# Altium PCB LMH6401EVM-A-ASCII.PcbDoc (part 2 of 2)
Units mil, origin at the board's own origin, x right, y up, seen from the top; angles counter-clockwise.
Board outline 1307 x 2660 mil, 6 copper layers (Top Layer L1, Layer 2 GND L2, Layer 3 V+ L3, Layer 4 V- L4, Layer 5 GND L5, Bottom Layer L6), stack 56.6 mil thick; 69 components, 33 nets, 203 pads, 373 vias.
Unrouted connection lines stored in the file: 2.
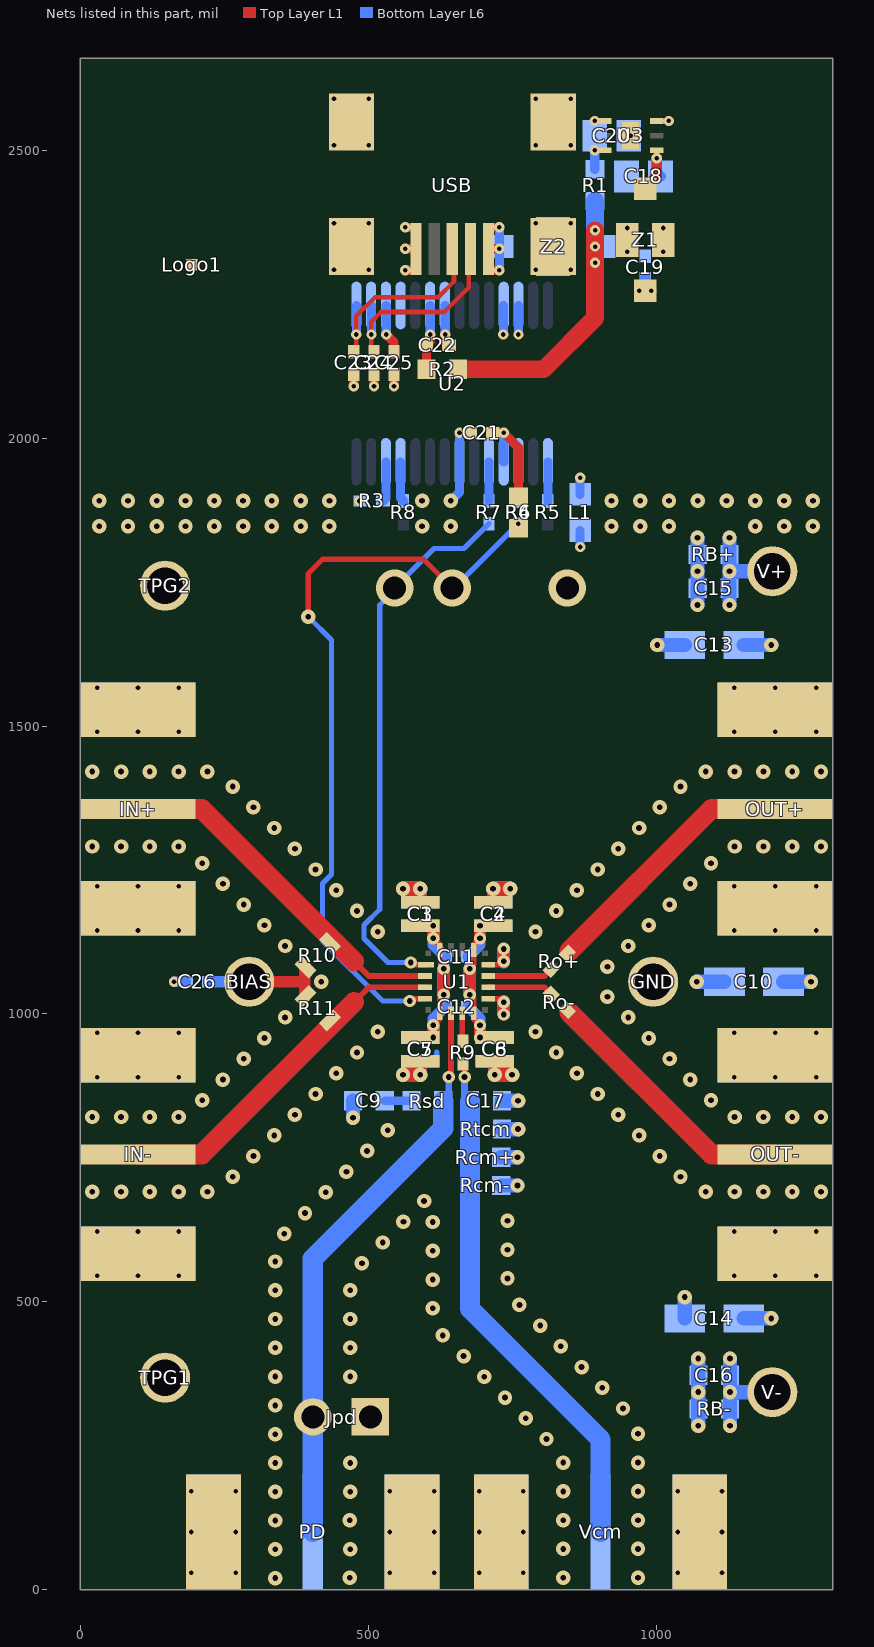
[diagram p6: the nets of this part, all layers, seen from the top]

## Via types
v1: diameter 25, hole 10, Top Layer L1 to Bottom Layer L6, tented both sides, 221 vias
v2: diameter 18, hole 8, Top Layer L1 to Bottom Layer L6, tented top, 73 vias
v3: diameter 18, hole 8, Top Layer L1 to Bottom Layer L6, tented both sides, 52 vias
v4: diameter 21.46, hole 10, Top Layer L1 to Bottom Layer L6, tented both sides, 22 vias
v5: diameter 64.96, hole 40, Top Layer L1 to Bottom Layer L6, 5 vias

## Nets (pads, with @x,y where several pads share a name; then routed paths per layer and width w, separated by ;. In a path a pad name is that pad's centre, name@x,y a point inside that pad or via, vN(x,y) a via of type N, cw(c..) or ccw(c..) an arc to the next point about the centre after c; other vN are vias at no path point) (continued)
GND: C1.1 C2.2 C3.2 C4.1 C5.2 C6.1 C7.1 C8.2 C9.2 C13.2 C14.1 C15.2 C16.2 C17.2 C26.1 GND.1 IN+.2 IN+.3 IN+.4 IN+.5 IN-.2 IN-.3 IN-.4 IN-.5 L1.1 OUT+.2 OUT+.3 OUT+.4 OUT+.5 OUT-.2 OUT-.3 OUT-.4 OUT-.5 PD.2 PD.3 PD.4 PD.5 RB+.1 RB-.2 Rtcm.2 TPG1.1 TPG2.1 U1.9 U1.12 Vcm.2 Vcm.3 Vcm.4 Vcm.5 | length 1069.1
  Top Layer L1 w9.84: U1.9@708.72,1026.47 729.16,1026.47 v4(735.2,1020.43) ; U1.12@708.72,1085.53 729.16,1085.53 v4(735.2,1091.57)
  Top Layer L1 w21.46: v4@735.2,999.05 v4(735.2,1020.43) ; v4(735.2,1091.57) v4@735.2,1112.95
  Top Layer L1 w22: v1(590.34,894.52) C5.2@590.34,918.02 ; C3.2@590.34,1193.98 v1(590.34,1217.48) ; C4.1@716.87,1193.98 v1(716.87,1217.48) ; v1(719.87,894.52) C6.1@719.87,918.02
  Top Layer L1 w25: v1(560.34,894.52) v1(590.34,894.52) ; v1(560.34,1217.48) v1(590.34,1217.48) ; v1(716.87,1217.48) v1(746.87,1217.48) ; v1(719.87,894.52) v1(749.87,894.52)
  Bottom Layer L6 w10: C7.1@590.34,918.02 618.84,918.02 618.84,933
  Bottom Layer L6 w16: v3(868,1811.32) L1.1@868,1840
  Bottom Layer L6 w18: v3(162.5,1056) C26.1@183.32,1056
  Bottom Layer L6 w21.46: v4@735.2,1001.13 v4@735.2,1022.5 ; v4@735.2,1089.58 v4@735.2,1110.96
  Bottom Layer L6 w22: v1(590.34,894.52) C7.1@590.34,918.02 ; C1.1@590.34,1193.98 v1(590.34,1217.48) ; C2.2@716.87,1193.98 v1(716.87,1217.48) ; v1(719.87,894.52) C8.2@719.87,918.02
  Bottom Layer L6 w25: v1(473.44,819.77) C9.2@473.44,849 ; v1(560.34,894.52) v1(590.34,894.52) ; v1(560.34,1217.48) v1(590.34,1217.48) ; v1(716.87,1217.48) v1(746.87,1217.48) ; v1(719.87,894.52) v1(749.87,894.52) ; Rtcm.2@732.06,800 v1(760.31,800) ; C17.2@732.06,849 v1(760.31,849) ; v1(1001.89,1641) C13.2@1049.82,1641 ; C14.1@1049.82,471 v1(1049.82,508.11) ; v1(1071.95,1710.54) v1(1071.95,1769) v1(1071.95,1827.46) ; v1(1073.44,284.54) v1(1073.44,343) v1(1073.44,401.46)
  other v1: 338.6,19.92 468,20.5 838.6,20.5 968.6,20.5 338.6,69.92 468.6,69.92 838.6,70.5 968.6,70.5 338.6,119.92 468,120.5 838.6,120.5 968.6,120.5 338.6,169.92 468.6,169.92 838.6,170.5 968.6,170.5 338.6,219.92 468.6,219.92 838.6,220.5 968.6,220.5 809.6,261.5 338.6,269.92 968.6,270.5 773.6,297.5 942.6,314.5 338.6,319.92 737.6,333.5 906.6,350.5 701.6,369.5 338.6,369.92 468.6,369.92 870.6,386.5 665.6,405.5 338.6,419.92 468.6,419.92 834.6,422.5 629.6,441.5 798.6,458.5 338.6,469.92 468.6,469.92 611.94,488.52 762.6,494.5 338.6,519.92 468.6,519.92 611.94,538.52 741.94,540.52 489,567 338.6,569.92 611.94,588.52 741.94,590.52 525,603 354,618 561,639 611.94,638.52 741.94,640.52 390,654 597,675 426,690 20.5,691 70.5,691 120.5,691 170.5,691 220.5,691 1086.5,691 1136.5,691 1186.5,691 1236.5,691 1286.5,691 264.5,717 1042.5,717 462,726 300.5,753 1006.5,753 498,762 336.5,789 970.5,789 534,798 20.5,821 70.5,821 120.5,821 170.5,821 1136.5,821 1186.5,821 1236.5,821 1286.5,821 372.5,825 934.5,825 211.5,850 1095.5,850 408.5,861 898.5,861 247.5,886 1059.5,886 444.5,897 862.5,897 283.5,922 1023.5,922 480.5,933 826.5,933 319.5,958 987.5,958 516.5,969 790.5,969 355.5,994 951.5,994 915.5,1030 418.5,1056 915.5,1082 355.5,1118 951.5,1118 516.5,1143 790.5,1143 319.5,1154 987.5,1154 480.5,1179 826.5,1179 283.5,1190 1023.5,1190 444.5,1215 862.5,1215 247.5,1226 1059.5,1226 408.5,1251 898.5,1251 211.5,1262 1095.5,1262 372.5,1287 934.5,1287 20.5,1291 70.5,1291 120.5,1291 170.5,1291 1136.5,1291 1186.5,1291 1236.5,1291 1286.5,1291 336.5,1323 970.5,1323 300.5,1359 1006.5,1359 264.5,1395 1042.5,1395 20.5,1421 70.5,1421 120.5,1421 170.5,1421 220.5,1421 1086.5,1421 1136.5,1421 1186.5,1421 1236.5,1421 1286.5,1421 32.5,1847.5 82.5,1847.5 132.5,1847.5 182.5,1847.5 232.5,1847.5 282.5,1847.5 332.5,1847.5 382.5,1847.5 432.5,1847.5 593.5,1847.5 643.5,1847.5 922.5,1847.5 972.5,1847.5 1022.5,1847.5 1172.5,1847.5 1222.5,1847.5 1272.5,1847.5
  other v2: 192.6,29 269.6,29 537.6,29 614.6,29 692.6,29 769.6,29 1037.6,29 1114.6,29 192.6,100 269.6,100 537.6,100 614.6,100 692.6,100 769.6,100 1037.6,100 1114.6,100 192.6,171 269.6,171 537.6,171 614.6,171 692.6,171 769.6,171 1037.6,171 1114.6,171 29,545 100,545 171,545 1136,545 1207,545 1278,545 29,622 100,622 171,622 1136,622 1207,622 1278,622 29,890 100,890 171,890 1136,890 1207,890 1278,890 29,967 100,967 171,967 1136,967 1207,967 1278,967 29,1145 100,1145 171,1145 1136,1145 1207,1145 1278,1145 29,1222 100,1222 171,1222 1136,1222 1207,1222 1278,1222 29,1490 100,1490 171,1490 1136,1490 1207,1490 1278,1490 29,1567 100,1567 171,1567 1136,1567 1207,1567 1278,1567
  other v4: 735.2,998.97 735.2,1113.03
  other v5: 845.75,1740
GND2: C18.2 C19.1 C20.2 C21.2 C22.2 C23.2 C24.2 C25.1 L1.2 Logo1.0 U2.7 U2.18 U2.21 U2.25 U2.26 U3.3 U3.7 USB.5 USB.6 USB.7 USB.8 USB.9 Z1.2 Z2.2 | length 558.6
  Top Layer L1 w9: U3.3@1001.29,2551.49 v3(1022.1,2551.49)
  Top Layer L1 w16: v3(474.96,2090.5) C23.2@474.96,2111.31 ; v3(509.96,2090.5) C24.2@509.96,2111.31 ; v3(544.75,2090.5) C25.1@544.75,2111.31 ; v3(564.16,2292.02) 583.01,2292.02 USB.5@583.01,2329.29 ; v3(564.16,2329.29) USB.5@583.01,2329.29 ; v3(564.16,2366.57) 583.01,2366.57 USB.5@583.01,2329.29 ; v3(633.7,2180.49) 633.7,2168.28 C22.2@640.34,2161.64 ; v3(658.54,2009.51) C21.2@677.24,2009.51
  Bottom Layer L6 w16: v3(633.7,2180.49) U2.21@633.7,2230.83 ; v1(643.5,1891.5) 658.54,1906.54 v3(658.54,2009.51) ; v3(734.82,2180.49) U2.25@734.82,2230.83 ; v3(760.91,2180.49) U2.26@760.91,2230.83 ; L1.2@868,1903 v3(868,1931.68)
  other v1: 32.5,1891.5 82.5,1891.5 132.5,1891.5 182.5,1891.5 232.5,1891.5 282.5,1891.5 332.5,1891.5 382.5,1891.5 432.5,1891.5 593.5,1891.5 922.5,1891.5 972.5,1891.5 1022.5,1891.5 1072.5,1891.5 1122.5,1891.5 1172.5,1891.5 1222.5,1891.5 1272.5,1891.5
  other v2: 956.02,2525.9
  other v3: 440.43,2293.02 501.17,2293.02 790.83,2293.02 851.57,2293.02 949.75,2324.47 1012.74,2324.47 949.75,2365.53 1012.74,2365.53 440.43,2373.44 501.17,2373.44 790.83,2373.44 851.57,2373.44 440.43,2509.55 501.17,2509.55 790.83,2509.55 851.57,2509.55 440.43,2589.98 501.17,2589.98 790.83,2589.98 851.57,2589.98
NetBIAS_1: BIAS.1 C26.2 R10.1 R11.2 | length 217.8
  Top Layer L1 w20: BIAS.1@293,1056 390,1056 ; R11.2@391.05,1031.21 390,1032.26 390,1056 ; R10.1@391.04,1080.79 390,1079.74 390,1056
  Bottom Layer L6 w20: C26.2@222.69,1056 BIAS.1@293,1056
NetC9_1: C9.1 Rsd.1 | length 46.6
  Bottom Layer L6 w15: C9.1@528.56,849 Rsd.1@575.15,849
NetC17_1: C17.1 R9.1 Rcm+.1 Rcm-.2 Rtcm.1 Vcm.1 | length 911.9
  Top Layer L1 w9: R9.1@664.5,913.32 667.41,910.4 v4(667.41,890.52)
  Bottom Layer L6 w12: v4(667.41,890.52) 667.41,857.53 C17.1@675.94,849
  Bottom Layer L6 w35: C17.1@676.94,849 Rtcm.1@676.94,800 676.94,487.34 903.6,260.68 Vcm.1@903.6,100
NetC18_1: C18.1 U3.1 Z1.3 | length 109.2
  Top Layer L1 w9: v3(1001.29,2486.38) U3.1@1001.29,2500.31
  Top Layer L1 w18: Z1.3@981.25,2433.58 981.25,2436.58 1001.29,2456.62 v3(1001.29,2486.38)
  Bottom Layer L6 w18: v3(1001.29,2486.38) 1001.29,2461.75 C18.1@1008.04,2455
NetC19_2: C19.2 C21.1 R3.2 R4.2 U2.4 Z1.1 | length 234.2
  Top Layer L1 w16: C21.1@716.61,2009.51 v3(735.32,2009.51) 760.91,1983.92 R4.2@760.91,1899.06
  Bottom Layer L6 w16: U2.4@735.32,1959.17 v3(735.32,2009.51)
  Bottom Layer L6 w18: v3(970.56,2256.42) v3(991.93,2256.42) ; 981.25,2256.42 C19.2@981.25,2279.2
  other v3: 484.27,1891.18
NetC20_1: C20.1 R1.1 U3.4 U3.6 | length 74.4
  Top Layer L1 w9: v3(893.53,2500.31) U3.6@914.34,2500.31 ; v3(893.53,2551.49) U3.4@914.34,2551.49
  Bottom Layer L6 w16: R1.1@893.53,2467.56 v3(893.53,2500.31)
NetC22_1: C22.1 R2.2 U2.20 | length 113.6
  Top Layer L1 w16: R2.2@600.97,2120 C22.1@600.97,2161.64 607.61,2168.28 v3(607.61,2180.49)
  Bottom Layer L6 w16: v3(607.61,2180.49) U2.20@607.61,2230.83
NetC23_1: C23.1 U2.15 USB.3 | length 366.6
  Top Layer L1 w8: C23.1@474.96,2150.68 479.41,2155.14 v3(479.41,2180.49) 479.41,2212.74 511.66,2245 621.5,2245 648.95,2272.45 648.95,2326.34 USB.3@646,2329.29
  Bottom Layer L6 w16: v3(479.41,2180.49) U2.15@479.41,2230.83
NetC24_1: C24.1 U2.16 USB.2 | length 366.4
  Top Layer L1 w8: C24.1@509.96,2150.68 505.5,2155.14 v3(505.5,2180.49) 505.5,2202.84 522.16,2219.5 632,2219.5 674.54,2262.04 674.54,2326.34 USB.2@677.49,2329.29
  Bottom Layer L6 w16: v3(505.5,2180.49) U2.16@505.5,2230.83
NetC25_2: C25.2 U2.17 | length 85.7
  Top Layer L1 w16: v3(531.34,2180.49) 544.75,2167.08 C25.2@544.75,2150.68
  Bottom Layer L6 w16: v3(531.34,2180.49) U2.17@531.34,2230.83
NetIN+_1: IN+.1 R10.2 U1.2 | length 618.7
  Top Layer L1 w9.84: 475.26,1091.42 500.84,1065.84 U1.2@598.48,1065.84
  Top Layer L1 w35: IN+.1@100,1356 210.68,1356 475.26,1091.42
NetIN-_1: IN-.1 R11.1 U1.3 | length 618.7
  Top Layer L1 w9.84: 475.26,1020.58 500.84,1046.16 U1.3@598.48,1046.16
  Top Layer L1 w35: IN-.1@100,756 210.68,756 475.26,1020.58
NetJpd_2: Jpd.2 PD.1 Rsd.2 U1.6 | length 1000.4
  Top Layer L1 w9.84: v4(639.79,890.52) 643.76,894.49 U1.6@643.76,1000.88
  Bottom Layer L6 w12: Rsd.2@630.27,849 639.79,858.53 v4(639.79,890.52)
  Bottom Layer L6 w35: PD.1@403.6,100 403.6,574.6 630.27,801.26 Rsd.2@630.27,849
NetOUT+_1: OUT+.1 Ro+.2 | length 459.1
  Top Layer L1 w35: Ro+.2@849.92,1109.6 1096.32,1356 OUT+.1@1207,1356
NetOUT-_1: OUT-.1 Ro-.2 | length 459.1
  Top Layer L1 w35: Ro-.2@849.92,1002.4 1096.32,756 OUT-.1@1207,756
NetR1_2: R1.2 R2.1 Z2.1 | length 535
  Top Layer L1 w31: R2.1@656.09,2120 805,2120 894.03,2209.03 v3(894.03,2361.63)
  Bottom Layer L6 w31: v3(894.03,2304.83) R1.2@894.03,2412.44
  other v3: 894.03,2333.23
NetR3_1: R3.1 U2.12 | length 70.1
  Bottom Layer L6 w16: R3.1@525.59,1891.18 530.59,1896.18 U2.12@530.59,1959.17
NetR5_2: R5.2 U2.1 | length 68
  Bottom Layer L6 w16: R5.2@812.09,1891.18 U2.1@812.09,1959.17
NetR6_2: R6.2 U2.3 | length 68
  Bottom Layer L6 w16: R6.2@760.91,1891.18 U2.3@760.91,1959.17
NetR7_2: R7.2 U2.5 | length 68
  Bottom Layer L6 w16: R7.2@709.72,1891.18 U2.5@709.72,1959.17
NetR8_2: R8.2 U2.11 | length 70.1
  Bottom Layer L6 w16: U2.11@556.18,1959.17 556.18,1896.18 R8.2@561.18,1891.18
NetR9_2: R9.2 U1.7 | length 48.6
  Top Layer L1 w10: U1.7@663.45,1000.88 663.45,953.74 R9.2@664.5,952.69
NetRo+_1: Ro+.1 U1.11 | length 114.2
  Top Layer L1 w9.84: U1.11@708.72,1065.84 806.16,1065.84 Ro+.1@818.01,1077.69
NetRo-_1: Ro-.1 U1.10 | length 114.2
  Top Layer L1 w9.84: U1.10@708.72,1046.16 806.16,1046.16 Ro-.1@818.01,1034.31
NetUSB_1: USB.1 Z2.3 | length 205.6
  Top Layer L1 w16: v3(727.83,2292.02) 708.99,2292.02 USB.1@708.99,2329.29 ; v3(727.83,2329.29) USB.1@708.99,2329.29 ; v3(727.83,2366.57) 708.99,2366.57 USB.1@708.99,2329.29
  Bottom Layer L6 w16: v3(727.83,2292.02) v3(727.83,2329.29) v3(727.83,2366.57)
SDI: R7.1 U1.1 | length 964
  Top Layer L1 w9.84: v4(573.97,1089.5) 577.94,1085.53 U1.1@600.45,1085.53
  Bottom Layer L6 w9: v5@545.75,1736.38 520,1710.63 520,1182 492.75,1154.75 492.75,1131.25 534.5,1089.5 v4(573.97,1089.5) ; v5(545.75,1740) 614.25,1808.5 666.41,1808.5 R7.1@709.72,1851.81
SDO: R4.1 R6.1 U1.4 | length 1323
  Top Layer L1 w9: v1(395.75,1690) 395.75,1765 420.75,1790 595.75,1790 v5(645.75,1740)
  Top Layer L1 w9.84: v4(572,1022.5) 575.97,1026.47 U1.4@598.48,1026.47
  Bottom Layer L6 w9: v1(395.75,1690) 436,1649.75 436,1242 420.75,1226.75 420.75,1126.76 525,1022.5 v4(572,1022.5) ; v5@649.09,1740 v3(760.91,1851.81)
V+: C2.1 C4.2 C6.2 C8.1 C10.1 C11.2 C12.2 C13.1 C15.1 Jpd.1 RB+.2 Rcm+.2 U1.8 U1.13 V+.1 | length 806.2
  Top Layer L1 w9.84: v4(676.13,1033.47) 683.13,1026.47 U1.8@683.13,1000.88 683.13,991.37 v4(694.1,980.4) ; v4(676.13,1078.53) 683.13,1085.53 U1.13@683.13,1111.12 683.13,1120.63 v4(694.1,1131.6)
  Top Layer L1 w21.46: v4(676.13,1033.47) v4(676.13,1078.53) ; C6.2@694.1,959.02 v4(694.1,980.4) ; v4(694.1,1131.6) 694.1,1152.98 C4.2@716.87,1152.98
  Bottom Layer L6 w19.68: v4(676.13,1033.47) 676.13,1015.74 C12.2@673.29,1012.9 694.1,992.09 v4(694.1,980.4) ; v4(676.13,1078.53) 676.13,1096.26 C11.2@673.29,1099.1 694.1,1119.91 v4(694.1,1131.6)
  Bottom Layer L6 w21.46: v4(676.13,1033.47) v4(676.13,1078.53) ; v4(694.1,958.94) C8.1@716.87,958.94 ; C8.1@694.1,959.02 v4(694.1,980.4) ; v4(694.1,1131.6) 694.1,1152.98 C2.1@716.87,1152.98
  Bottom Layer L6 w25: Rcm+.2@731.06,751 v1(759.31,751) ; v1(1070.89,1056) C10.1@1118.82,1056 ; v1(1127.56,1710.54) v1(1127.56,1769) ; v1(1127.56,1827.46) RB+.2@1127.56,1798.23 v1(1127.56,1769) ; C13.1@1152.18,1641 v1(1200.11,1641) ; V+.1@1202,1769 v1(1127.56,1769)
  other v4: 694.1,1153.06
V-: C1.2 C3.1 C5.1 C7.2 C10.2 C11.1 C12.1 C14.2 C16.1 RB-.1 Rcm-.1 U1.5 U1.16 V-.1 | length 828.9
  Top Layer L1 w9.84: v4(613.11,980.4) 624.08,991.37 U1.5@624.08,1000.88 624.08,1026.47 v4(631.08,1033.47) ; v4(613.11,1131.6) 624.08,1120.63 U1.16@624.08,1111.12 624.08,1093.61 631.08,1086.61 v4(631.08,1078.53)
  Top Layer L1 w21.46: C5.1@590.34,959.02 613.11,959.02 v4(613.11,980.4) ; C3.1@590.34,1152.98 613.11,1152.98 v4(613.11,1131.6) ; v4(631.08,1033.47) v4(631.08,1078.53)
  Bottom Layer L6 w19.68: v4(613.11,980.4) 613.11,992.09 C12.1@633.92,1012.9 631.08,1015.74 v4(631.08,1033.47) ; v4(613.11,1131.6) 613.11,1119.91 C11.1@633.92,1099.1 631.08,1096.26 v4(631.08,1078.53)
  Bottom Layer L6 w21.46: C7.2@590.34,959.02 613.11,959.02 v4(613.11,980.4) ; C1.2@590.34,1152.98 613.11,1152.98 v4(613.11,1131.6) ; v4(631.08,1033.47) v4(631.08,1078.53)
  Bottom Layer L6 w25: Rcm-.1@731.06,702 v1(759.31,702) ; v1(1128.56,284.54) RB-.1@1128.56,313.77 v1(1128.56,343) ; v1(1128.56,401.46) C16.1@1128.56,372.23 v1(1128.56,343) ; C14.2@1152.18,471 v1(1200.11,471) ; V-.1@1203,343 v1(1128.56,343) ; C10.2@1221.18,1056 v1(1269.11,1056)
  other v4: 613.11,958.94 613.11,1153.06
pads on no net: U1. U2.2 U2.6 U2.8 U2.9 U2.10 U2.13 U2.14 U2.19 U2.22 U2.23 U2.24 U2.27 U2.28 U3.2 U3.5 USB.4

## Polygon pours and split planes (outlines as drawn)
GND on Top Layer L1 "Top Layer L1-GND" (solid, remove dead copper, pour order 6): 0,0 0,1860 1307,1860 1307,0
GND2 on Top Layer L1 "Top Layer L1-GND2" (solid, pour order 8): 1307,2660 1307,1879 0,1879 0,2660
GND2 on Bottom Layer L6 "Bottom Layer L6-GND2" (solid, pour order 7): 1307,2660 1307,1879 0,1879 0,2660
GND on Bottom Layer L6 "Bottom Layer L6-GND" (solid, remove dead copper, pour order 5): 0,0 0,1860 1307,1860 1307,0
GND2 on Layer 2 GND L2 (split plane): 1306.95,1879.08 0.05,1879.08 0.05,2659.95 1306.95,2659.95
GND on Layer 2 GND L2 (split plane): 1306.95,0.05 0.05,0.05 0.05,1859.92 1306.95,1859.92
NetC19_2 on Layer 3 V+ L3 (split plane): 1286.9,1879.08 20.1,1879.08 20.1,2639.9 1286.9,2639.9
V+ on Layer 3 V+ L3 (split plane): 1286.9,20.1 20.1,20.1 20.1,1859.92 1286.9,1859.92
GND2 on Layer 4 V- L4 (split plane): 1286.9,1879.08 20.1,1879.08 20.1,2639.9 1286.9,2639.9
V- on Layer 4 V- L4 (split plane): 1286.9,20.1 20.1,20.1 20.1,1859.92 1286.9,1859.92
GND2 on Layer 5 GND L5 (split plane): 1306.95,1879.08 0.05,1879.08 0.05,2659.95 1306.95,2659.95
GND on Layer 5 GND L5 (split plane): 1306.95,0.05 0.05,0.05 0.05,1859.92 1306.95,1859.92

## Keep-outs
Keep-Out Layer:
  text ".Layer_Name" at 577,-858.49 h60

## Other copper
Top Layer L1:
  text ".Layer_Name" at 577,-858.49 h60
Bottom Layer L6:
  text ".Layer_Name" at 577,-858.49 h60
Layer 2 GND L2 (plane layer: these items are gaps in the copper):
  lines w0.1: 0,0 0,2660 1307,2660 1307,0 0,0
  lines w19: 0,1869.5 1307,1869.5
  text ".Layer_Name" at 577,-858.49 h60
Layer 5 GND L5 (plane layer: these items are gaps in the copper):
  lines w0.1: 0,0 0,2660 1307,2660 1307,0 0,0
  lines w19: 0,1869.5 1307,1869.5
  text ".Layer_Name" at 577,-858.49 h60
Layer 3 V+ L3 (plane layer: these items are gaps in the copper):
  lines w19: 0,1869.5 1307,1869.5
  lines w40: 0,0 0,2660 1307,2660 1307,0 0,0
  text ".Layer_Name" at 577,-858.49 h60
Layer 4 V- L4 (plane layer: these items are gaps in the copper):
  lines w19: 0,1869.5 1307,1869.5
  lines w40: 0,0 0,2660 1307,2660 1307,0 0,0
  text ".Layer_Name" at 577,-858.49 h60

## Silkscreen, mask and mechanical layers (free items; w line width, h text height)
Top Overlay:
  text "GND" at 865,1585 h40 r90
  text "*CS" at 465,1575 h40 r90
  text "SDI" at 565,1575 h40 r90
  text "SDO" at 665,1575 h40 r90
  text "CLK" at 765,1575 h40 r90
  text ".PRJ_Title" at 372,550 h50
  text ".PRJ_Number" at 372,425 h40
  text ".PCB_Rev" at 662,425 h40
  text "-" at 732,425 h40
  text ".Layer_Name" at 577,-858.49 h60
Bottom Overlay:
  text "UL94V-0" at 1162,1975 h60 r270
  text "MADE IN U.S." at 162,1925 h60 r270
  text "TI" at 321.97,354 h60
  text ".CopyrightYear" at 597.97,354 h60
  text "©" at 714.97,350.48 h105
  text ".Layer_Name" at 577,-858.49 h60
Top Paste:
  text ".Layer_Name" at 577,-858.49 h60
Bottom Paste:
  text ".Layer_Name" at 577,-858.49 h60
Top Solder:
  lines w14.7: 475.26,1020.58 500.84,1046.16 598.48,1046.16 ; 475.26,1091.42 500.84,1065.84 598.48,1065.84 ; 708.72,1046.16 806.16,1046.16 818.01,1034.31 ; 708.72,1065.84 806.16,1065.84 818.01,1077.69
  lines w41: 100,756 210.36,756 474.94,1020.58 ; 100,1356 210.36,1356 474.94,1091.42 ; 849.92,1002.4 1096.32,756 1207,756 ; 849.92,1109.6 1096.32,1356 1207,1356
  lines w65: 0,1869.5 701,1869.5 ; 820,1869.5 1307,1869.5
  text ".Layer_Name" at 577,-858.49 h60
  text ".Layer_Name" at 577,-858.49 h60
Bottom Solder:
  lines w65: 0,1869.5 432,1869.5 ; 932,1869.5 1307,1869.5
  text ".Layer_Name" at 577,-858.49 h60
Drill Guide:
  text ".Layer_Name" at 577,-858.49 h60
M1 Board Outline:
  the board outline again, w10
  text ".Layer_Name" at 577,-858.49 h60
M2 Board Dimensions:
  rectangle: -0.5,-285.5 124.5,-160.5
  rectangle: 124.5,-410.5 499.5,-285.5
  lines w7: -0.5,-285.5 999.5,-285.5 ; 124.5,-410.5 124.5,-160.5 ; 249.5,-410.5 249.5,-160.5 ; 499.5,-410.5 499.5,-160.5 ; 749.5,-410.5 749.5,-160.5 ; -0.5,-410.5 999.5,-410.5 999.5,-160.5 -0.5,-160.5 -0.5,-410.5
  text ".Layer_Name" at 577,-858.49 h60
M3 3D STEP Top:
  text ".Layer_Name" at 577,-858.49 h60
M4 3D STEP Bottom:
  text ".Layer_Name" at 577,-858.49 h60
M5 Assembly Top:
  lines w10: -292,-930.17 6308,-930.17 ; -292,-726.83 6310,-726.83 ; -292,-523.5 -292,-1133.5 3713,-1133.5 6310,-1133.5 6310,-523.5 -291.5,-523.5 -291.5,-1133.5 1284,-1133.5 ; 2173,-1133.5 2173,-523.5 ; 3440,-726.83 3440,-523.5 ; 4280,-726.83 4280,-523.5 ; 4902,-1140 4902,-937.17
  text "COMPONENTS MARKED 'DNP' SHOULD NOT BE POPULATED." at 1153.5,-318.5 h60
  text "ASSEMBLY VARIANT:" at 1153,-434 h60
  text ".VariantName" at 2189,-434 h60
  text "PCB VIEWED FROM TOP SIDE" at -228.5,-655.67 h60
  text "BOARD #:" at 2248,-655.67 h60
  text ".PRJ_Number" at 2793.5,-655.67 h60
  text "REV:" at 3638,-655.67 h60
  text ".PCB_Rev" at 3929.5,-655.67 h60
  text "SVN REV:" at 4476,-655.67 h60
  text ".VersionControl_RevNumber" at 4982,-655.67 h60
  text "IGNORE ->" at -228.5,-858.49 h60
  text "PLOT NAME =" at -228.5,-1064.34 h60
  text ".plot_File_Name" at 577,-1064.34 h60
  text "GENERATED    :" at 2250,-1064.34 h60
  text ".Print_Date" at 3119.5,-1064.34 h60
  text ".Print_Time" at 3848.5,-1064.34 h60
  text "TEXAS INSTRUMENTS" at 5113,-1064.34 h60
M6 Assembly Bottom:
  lines w10: -292.5,-727.33 6309.5,-727.33 ; -290.5,-930.67 6309.5,-930.67 ; 1115.5,-1140.5 1115.5,-937.67 ; 1737.5,-727.33 1737.5,-524 ; 2577.5,-727.33 2577.5,-524 ; 3844.5,-1134 3844.5,-524 ; 4733.5,-1134 6309,-1134 6309,-524 -292.5,-524 -292.5,-1134 2304.5,-1134 6309.5,-1134 6309.5,-524
  text "COMPONENTS MARKED 'DNP' SHOULD NOT BE POPULATED." at 6102,-318 h60
  text ".VariantName" at 5058,-434 h60
  text "ASSEMBLY VARIANT:" at 6097,-434 h60
  text ".VersionControl_RevNumber" at 1035.5,-656.17 h60
  text "SVN REV:" at 1541.5,-656.17 h60
  text ".PCB_Rev" at 2088,-656.17 h60
  text "REV:" at 2379.5,-656.17 h60
  text ".PRJ_Number" at 3224,-656.17 h60
  text "BOARD #:" at 3769.5,-656.17 h60
  text "PCB VIEWED FROM BOTTOM SIDE" at 6246,-656.17 h60
  text "IGNORE ->" at 2547.85,-858.49 h60
  text "TEXAS INSTRUMENTS" at 904.5,-1064.84 h60
  text ".Print_Time" at 2169,-1064.84 h60
  text ".Print_Date" at 2898,-1064.84 h60
  text "GENERATED    :" at 3767.5,-1064.84 h60
  text ".plot_File_Name" at 5440.5,-1064.84 h60
  text "PLOT NAME =" at 6246,-1064.84 h60
M9 Title Sheet:
  lines w10: -491.5,1041.5 -291.5,1041.5 ; -491.5,3416.5 -291.5,3416.5 ; -491.5,5791.5 -291.5,5791.5 ; 2008.5,-1333.5 2008.5,-1133.5 ; 2008.5,7966.5 2008.5,8166.5 ; 4508.5,-1333.5 4508.5,-1133.5 ; 4508.5,7966.5 4508.5,8166.5 ; 6321,-1133.5 6321,-523.5 11303.5,-523.5 ; 7008.5,-1333.5 7008.5,-1133.5 ; 7008.5,7966.5 7008.5,8166.5 ; 9508.5,-1333.5 9508.5,-1133.5 ; 9508.5,7966.5 9508.5,8166.5 ; 11303.5,-1133.5 11303.5,-523.5 ; 11303.5,-823.5 14303.5,-823.5 ; 11303.5,-223.5 14303.5,-223.5 ; 11304.5,370.5 14304.5,370.5 ; 12008.5,-1333.5 12008.5,-1133.5 ; 12008.5,7966.5 12008.5,8166.5 ; 12808.5,-1123.5 12808.5,-523.5 ; 14303.5,-523.5 11303.5,-523.5 ; 14303.5,76.5 11303.5,76.5 ; 14308.5,66.5 14308.5,-1133.5 ; 14308.5,871 11304.5,871 11303.5,871 11303.5,370.5 11303.5,76.5 ; 14308.5,1041.5 14508.5,1041.5 ; 14308.5,3416.5 14508.5,3416.5 ; 14308.5,5791.5 14508.5,5791.5 ; 11303.5,-523.5 11303.5,76.5 ; 14308.5,-1133.5 14308.5,7966.5 -291.5,7966.5 -291.5,-1133.5 14308.5,-1133.5 ; -491.5,-1333.5 -491.5,8166.5 14508.5,8166.5 14508.5,-1333.5 -491.5,-1333.5
  text "1" at 739.84,8036.5 h70
  text "2" at 3235.5,8036.5 h70
  text "3" at 5724.84,8036.5 h70
  text "4" at 8231.51,8036.5 h70
  text "5" at 10730.5,8036.5 h70
  text "6" at 13235.5,8036.5 h70
  text "A" at -416.5,6893.5 h70
  text "A" at 14383.5,6893.5 h70
  text "B" at -416.5,4513.5 h70
  text "B" at 14383.5,4513.5 h70
  text "C" at -416.5,2138.5 h70
  text "C" at 14383.5,2138.5 h70
  text "PROJECT TITLE:" at 11343.5,277.5 h45
  text ".PRJ_Title" at 11393.5,144.17 h70
  text "DESIGNED FOR:" at 11343.5,-23.5 h45
  text ".PRJ_Customer" at 11393.5,-163.5 h70
  text "D" at -416.5,-231.5 h70
  text "D" at 14383.5,-231.5 h70
  text "FILE NAME:" at 11343.5,-323.5 h45
  text ".PCB_File_Name_No_Path" at 11393.5,-443.5 h70
  text "Texas Instruments (TI) and/or its licensors do not warrant the accuracy or completeness of this specification" at 6374,-605.34 h45
  text "ENGINEER:" at 11343.5,-613.5 h45
  text "LAYOUT BY:" at 12848.5,-613.5 h45
  text "or any information contained therein. TI and/or its licensors do not warrant that this design will meet" at 6329.01,-718 h45
  text ".PRJ_Engineer" at 11393.5,-768.49 h70
  text ".PCB_Layout" at 12899,-768.49 h70
  text "the specifications, will be suitable for your application or fit for any particular purpose, or will operate in" at 6329.01,-830.67 h45
  text ".Layer_Name" at 577,-858.49 h60
  text "ALTIUM DESIGNER VERSION:" at 12848.5,-923.5 h45
  text "an implementation. TI and/or its licensors do not warrant that the design is production worthy. You should" at 6329.01,-943.33 h45
  text "completely validate and test your design implementation to confirm the system functionality for your application." at 6374,-1056 h45
  text ".print_Scale" at 11393.5,-1056.83 h70
  text ".Application_BuildNumber" at 12899,-1056.83 h70
  text "1" at 739.84,-1263.5 h70
  text "2" at 3235.5,-1263.5 h70
  text "3" at 5724.84,-1263.5 h70
  text "4" at 8231.51,-1263.5 h70
  text "5" at 10730.5,-1263.5 h70
  text "6" at 13235.5,-1263.5 h70
M10 Fab Notes:
  drawing of 212 lines, arcs and shapes, not listed
  text "DESIGN INFORMATION" at 12381.02,6810 h60
  text "(REFER ALSO ARRAY/PANEL PROFILING INFORMATION)" at 12019.46,6648.29 h60
  text "BOARD SIZE" at 11333.46,6644 h60
  text "X" at 12301.46,6516.18 h60
  text "Number of Layers :" at 11736.46,6319 h60
  text "6" at 12831.27,6309 h60
  text "MIN. TRACK WIDTH:" at 11736.46,6180 h60
  text "8" at 12832.7,6180 h60
  text "MIL" at 12987.46,6180 h60
  text "MIN. CLEARANCE:" at 11736.46,6048 h60
  text "8" at 12832.7,6048 h60
  text "MIL" at 12987.46,6048 h60
  text "MIN. VIA PAD SIZE:" at 11736.46,5916 h60
  text "21" at 12802.71,5916 h60
  text "MIL" at 12987.46,5916 h60
  text "0.05mm (2MIL)" at 12431.46,5774.29 h60
  text "MINIMUM ANNULAR RING" at 11407.23,5770 h60
  text "EXTERNAL" at 13139.46,5770 h60
  text "PER" at 11607.23,5652 h60
  text "IPC-D-275 CLASS 2 LEVEL C" at 11827.23,5652 h60
  text "MIL, HOLES" at 13315.46,5539.71 h60
  text "+/-" at 12923,5539 h60
  text "+/-" at 13777,5539 h60
  text "REGISTRATION TOLERANCES:" at 11407.23,5534 h60
  text "METAL" at 12607,5534 h60
  text "5" at 13183.2,5534 h60
  text "3" at 14016.2,5534 h60
  text "MIL" at 14132.46,5534 h60
  text "MATERIAL:" at 11332.46,5324.54 h60
  text "FR-4 High Tg" at 12318.9,5184.21 h60
  text "FR-408" at 11753.46,5175.64 h60
  text "X" at 12165.46,5175.64 h60
  text "X" at 13054.46,5176 h60
  text "OTHER   ROGERS 4350" at 13241.46,5175.64 h60
  text "62 MIL (1.6mm) +/-10%" at 12073.56,5012.92 h60
  text "THICKNESS:" at 11407.23,5008.64 h60
  text "X" at 11945.4,5008.64 h60
  text "OTHER" at 13358.46,5008.64 h60
  text "TOLERANCE:" at 11407.23,4850.64 h60
  text "X" at 12246.53,4850.64 h60
  text "ANSI IPC-6012 TYPE 3 CLASS 2" at 12433.48,4850.64 h60
  text "OTHER +/-" at 12433.46,4694.64 h60
  text "BOW & TWIST:" at 11407.23,4537.64 h60
  text "X" at 12246.53,4537.64 h60
  text "ANSI IPC-6012 TYPE 3 CLASS 2" at 12433.48,4537.64 h60
  text "OTHER +/-" at 12433.46,4379.13 h60
  text "COPPER THICKNESS (FINISHED):" at 11332.46,4243.64 h60
  text "1.4MIL (1oz)" at 12212.46,4090.92 h60
  text "2MIL (1.4oz)" at 12979.46,4090.92 h60
  text "2.8MIL (2oz)" at 13706.46,4090.92 h60
  text "OUTER:" at 11689.46,4086.64 h60
  text "X" at 12084,4086 h60
  text "1.4MIL (1oz)" at 12212.46,3933.92 h60
  text "2.8MIL (2oz)" at 12979.46,3933.92 h60
  text "N/A" at 13706,3934.29 h60
  text "INNER SIGNAL:" at 11400.38,3929.64 h60
  text "X" at 12085.42,3929.64 h60
  text "DRILLING:" at 11332.46,3790.64 h60
  text "REFERENCE:" at 11407.23,3673.64 h60
  text "X" at 12055.46,3673.64 h60
  text "AS SHOWN" at 12242.46,3673.64 h60
  text "X" at 12956.46,3673.64 h60
  text "NC_DRILL FILES" at 13093.46,3673.64 h60
  text "PTH MIN COPPER THICKNESS:" at 11407.23,3515.64 h60
  text "X" at 12757.46,3515.64 h60
  text "1MIL" at 12894.46,3515.64 h60
  text "OTHER" at 13391.46,3515.64 h60
  text "BOARD FINISH:" at 11332.46,3356.64 h60
  text "SILKSCREEN:" at 11487.68,3238.64 h60
  text "X" at 12436.46,3238.64 h60
  text "TOP" at 12562.46,3238.64 h60
  text "X" at 12946.46,3238.64 h60
  text "BOTTOM" at 13073.46,3238.64 h60
  text "SILKSCREEN COLOR:" at 11487.68,3071.64 h60
  text "X" at 12435.42,3071.64 h60
  text "WHITE" at 12562.46,3071.64 h60
  text "OTHER" at 13073.46,3071.64 h60
  text "SOLDER RESIST COLOR:" at 11487.68,2901.64 h60
  text "X" at 12055.42,2742.44 h60
  text "GREEN" at 12182.46,2742.44 h60
  text "BLUE" at 12773.46,2742.44 h60
  text "OTHER" at 13311.46,2742.44 h60
  text "IMMERSION GOLD (ENIG)" at 12393.46,2553.92 h60
  text "ENEPIG" at 13731,2550.64 h60
  text "SURFACE FINISH:" at 11332.46,2549.64 h60
  text "X" at 12206.51,2549.64 h60
  text "IMM. TIN/SILVER OR EQUIV" at 11662,2392.64 h60
  text "OTHER" at 13093.46,2392.64 h60
  text "ARRAY/PANEL:" at 11332.46,2213.64 h60
  text "CUT AND TRIM PER MECH LAYER 1" at 12393.46,2209.35 h60
  text "N.C. ROUTE" at 12393.46,2057.64 h60
  text "X" at 13072.46,2057.64 h60
  text "V. SCORE" at 13259.46,2057.64 h60
  text "CERTIFICATION:" at 11332.46,1920.64 h60
  text "MATERIALS AND WORKMANSHIP FOR ALL PCBS" at 12057.46,1920.64 h60
  text "TO MEET OR EXCEED THE REQUIREMENTS OF:" at 12057.46,1822.64 h60
  text "Single ended tracks 50 ohms Top Layer equal 35mils width." at 3833,1820 h100
  text "X" at 11683.96,1686.13 h60
  text "ANSI IPC-A-600F CLASS ->" at 11822.96,1686.13 h60
  text "X" at 13462.02,1686.13 h60
  text "2" at 13580.96,1686.14 h60
  text "1" at 13265.96,1684.64 h60
  text "3" at 13934.96,1684.64 h60
  text "X" at 11686.02,1526.64 h60
  text "UL 94V-0" at 11822.96,1526.64 h60
  text "X" at 12498.02,1526.64 h60
  text "RoHS" at 12634.96,1526.64 h60
  text "OTHER" at 13279.36,1526.64 h60
  text "PER ORDER" at 13676.42,1526.64 h60
  text "ADDITIONAL REQUIREMENTS:" at 11332.46,1385.64 h60
  text "MICROSECTION:" at 11407.23,1270.64 h60
  text "YES" at 12312.96,1270.64 h60
  text "REQUIRED" at 13174.46,1114.49 h60
  text "BARE BOARD ELEC. TEST:" at 11407.23,1111.64 h60
  text "NONE" at 12712.96,1111.64 h60
  text "X" at 13047.46,1111.64 h60
  text "PER ORDER" at 13766.46,1111.64 h60
  text "MANUFACTURER'S UL:" at 11407.23,954.64 h60
  text "RAIL" at 12572.96,950.35 h60
  text "METAL" at 13064.77,950.35 h60
  text "X" at 13440,950 h60
  text "SILK" at 13576.46,950.35 h60
  text ".Layer_Name" at 577,-858.49 h60
M11 Gerber Information:
  lines w10: -292,-930.17 6308,-930.17 ; -292,-726.83 6310,-726.83 ; -292,-523.5 -292,-1133.5 3713,-1133.5 6310,-1133.5 6310,-523.5 -291.5,-523.5 -291.5,-1133.5 1284,-1133.5 ; 2173,-1133.5 2173,-523.5 ; 3440,-726.83 3440,-523.5 ; 4280,-726.83 4280,-523.5 ; 4902,-1140 4902,-937.17
  text "ALL ARTWORK VIEWED FROM TOP SIDE" at -228.5,-655.67 h60
  text "BOARD #:" at 2248,-655.67 h60
  text ".PRJ_Number" at 2793.5,-655.67 h60
  text "REV:" at 3638,-655.67 h60
  text ".PCB_Rev" at 3929.5,-655.67 h60
  text "SVN REV:" at 4476,-655.67 h60
  text ".VersionControl_RevNumber" at 4982,-655.67 h60
  text "LAYER NAME =" at -228.5,-858.49 h60
  text "PLOT NAME =" at -228.5,-1064.34 h60
  text ".plot_File_Name" at 577,-1064.34 h60
  text "GENERATED    :" at 2250,-1064.34 h60
  text ".Print_Date" at 3119.5,-1064.34 h60
  text ".Print_Time" at 3848.5,-1064.34 h60
  text "TEXAS INSTRUMENTS" at 5113,-1064.34 h60
M12 Stackup:
  lines w5: 11364,7753.1 14227,7753.1 ; 11364,7848.3 14227,7848.3 ; 11304,6980 ccw(c11335,6980) 11335,6949 14256,6949 ccw(c14256,6980) 14287,6980 14287,7920 ccw(c14256,7920) 14256,7951 11335,7951 ccw(c11335,7920) 11304,7920 11304,6980
  text "Layer Stack Up Detail for: LMH6401_rev_a.PcbDoc" at 11364,7870.95 h39
  text "Layer" at 11364,7812.8 h22
  text "Gerber" at 11975,7812.8 h22
  text "Copper" at 12286.16,7812.8 h22
  text "Dielectric" at 12633.24,7812.8 h22
  text "Dielectric" at 12995.72,7812.8 h22
  text "Dielectric" at 13451.76,7812.8 h22
  text "Dielectric" at 13814.24,7812.8 h22
  text "Name" at 11364,7768.8 h22
  text "Document" at 11975,7768.8 h22
  text "Thickness" at 12286.16,7768.8 h22
  text "Height" at 12633.24,7768.8 h22
  text "Material" at 12995.72,7768.8 h22
  text "Constant" at 13451.76,7768.8 h22
  text "Type" at 13814.24,7768.8 h22
  text "Top Solder Mask" at 11364,7706.76 h31
  text "(.GTS)" at 11975,7706.76 h31
  text "0.4mil" at 12633.24,7706.76 h31
  text "Solder Resist" at 12995.72,7706.76 h31
  text "3.50" at 13451.76,7706.76 h31
  text "Top Layer L1" at 11364,7619.09 h31
  text "(.GTL)" at 11975,7619.09 h31
  text "1.4mil" at 12286.16,7619.09 h31
  text "16.6mil" at 12633.24,7575.25 h31
  text "Rogers RO4350" at 12995.72,7575.25 h31
  text "3.66" at 13451.76,7575.25 h31
  text "Core" at 13814.24,7575.25 h31
  text "Layer 2 GND L2" at 11364,7531.41 h31
  text "(.GP1)" at 11975,7531.41 h31
  text "1.4mil" at 12286.16,7531.41 h31
  text "5mil" at 12633.24,7487.58 h31
  text "FR406" at 12995.72,7487.58 h31
  text "4.80" at 13451.76,7487.58 h31
  text "PrePreg" at 13814.24,7487.58 h31
  text "Layer 3 V+ L3" at 11364,7443.74 h31
  text "(.GP2)" at 11975,7443.74 h31
  text "1.4mil" at 12286.16,7443.74 h31
  text "5mil" at 12633.24,7399.9 h31
  text "FR406" at 12995.72,7399.9 h31
  text "4.80" at 13451.76,7399.9 h31
  text "Core" at 13814.24,7399.9 h31
  text "Layer 4 V- L4" at 11364,7356.06 h31
  text "(.GP3)" at 11975,7356.06 h31
  text "1.4mil" at 12286.16,7356.06 h31
  text "5mil" at 12633.24,7312.23 h31
  text "FR406" at 12995.72,7312.23 h31
  text "4.80" at 13451.76,7312.23 h31
  text "PrePreg" at 13814.24,7312.23 h31
  text "Layer 5 GND L5" at 11364,7268.39 h31
  text "(.GP4)" at 11975,7268.39 h31
  text "1.4mil" at 12286.16,7268.39 h31
  text "16.6mil" at 12633.24,7224.55 h31
  text "FR406" at 12995.72,7224.55 h31
  text "4.80" at 13451.76,7224.55 h31
  text "Core" at 13814.24,7224.55 h31
  text "Bottom Layer L6" at 11364,7180.71 h31
  text "(.GBL)" at 11975,7180.71 h31
  text "1.4mil" at 12286.16,7180.71 h31
  text "Bottom Solder Mask" at 11364,7093.04 h31
  text "(.GBS)" at 11975,7093.04 h31
  text "0.4mil" at 12633.24,7093.04 h31
  text "Solder Resist" at 12995.72,7093.04 h31
  text "3.50" at 13451.76,7093.04 h31
  text ".Layer_Name" at 577,-858.49 h60
M13 Component Bodies Top:
  text ".Layer_Name" at 577,-858.49 h60
M14 Component Bodies Bottom:
  text ".Layer_Name" at 577,-858.49 h60
M15 Courtyards Top:
  text ".Layer_Name" at 577,-858.49 h60
M16 Courtyards Bottom:
  text ".Layer_Name" at 577,-858.49 h60
Drill Drawing:
  text ".legend" at 5122.5,725.5 h60
  text "Drill Table" at 5147.5,540.5 h60
  text ".Layer_Name" at 577,-858.49 h60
